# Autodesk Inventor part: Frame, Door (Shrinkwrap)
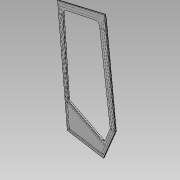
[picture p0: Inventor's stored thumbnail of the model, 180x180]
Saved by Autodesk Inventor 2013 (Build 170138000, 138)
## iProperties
Created: 2012-10
Part Number: Frame, Door (Shrinkwrap)
Material: Generic
Document SubType Name: Modeling
Designer: VMuser
Density: 1 g/cm^3
Author: VMuser
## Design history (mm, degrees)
derived "Frame, Door.iam"
body "Solid1"
node "PK46.51.11.011.ipt:1"
node "PK46.51.11.014.ipt:1"
node "PK46.51.11.013.ipt:1"
node "PK46.51.11.021.ipt:1"
node "PK46.51.11.023.ipt:1"
node "PK46.51.11.025.ipt:1"
node "PK46.51.11.024.ipt:1"
node "PK46.51.11.031.ipt:1"
node "PK46.51.11.033.ipt:1"
node "PK46.51.11.035.ipt:1"
node "PK46.51.11.034.ipt:1"
node "PK46.51.11.022.ipt:1"
node "PK46.51.11.032.ipt:1"
node "Support gas.ipt:1"
node "PK46.51.11.026.ipt:1"
node "PK46.51.11.016-01.ipt:1"
node "PK46.51.11.016.ipt:1"
node "PK46.51.11.012(new).ipt:1"
node "Frame, Door.iam_Bodies"
